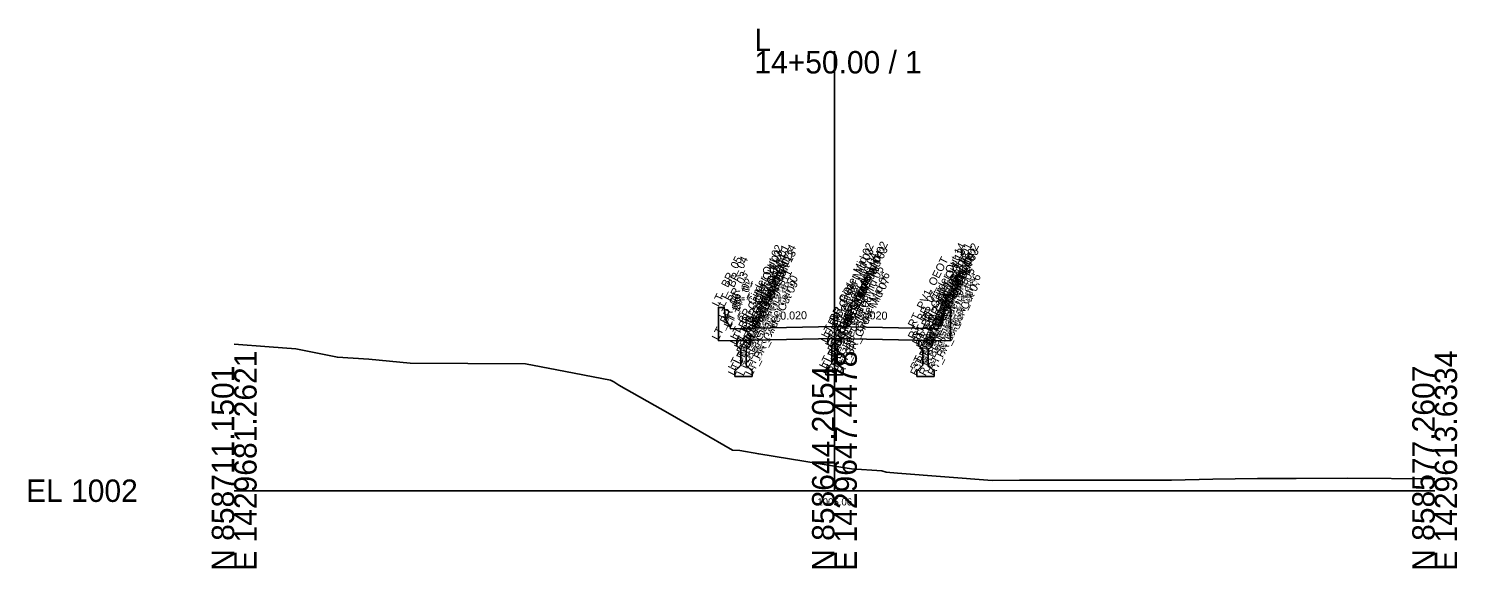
# Model space of a CAD drawing. Extents: x -26 to 153, y -10 to 13058.
# Drawn here: x -25.7 to 152.8, y 5990.3 to 6057.7 of the extents above; entities that cross this region are included whole.
import ezdxf

# ---------------------------------------------------------------- set-up
doc = ezdxf.new("R2010")
doc.units = 0
for name, color, linetype in [('Default', 7, 'Continuous'), ('Exist Cross Section Cell', 7, 'Continuous'), ('Exist XS Ground Line', 7, 'Continuous'), ('Prop CMT Concrete Structures', 7, 'Continuous'), ('Prop CMT Subgrade Daylight Point', 7, 'Continuous'), ('Prop XS Dump Level', 7, 'Continuous'), ('Prop XS SE Text', 7, 'Continuous')]:
    doc.layers.add(name, color=color, linetype=linetype)

msp = doc.modelspace()

# ---------------------------------------------------------------- linework, layer by layer
at = {"layer": 'Exist Cross Section Cell'}
for p, q in [((75, 6000), (75, 6054.87)), ((0, 6000), (75, 6000)), ((75, 6000), (150, 6000))]:
    msp.add_line(p, q, dxfattribs=at)
at = {"layer": 'Exist XS Ground Line'}
msp.add_lwpolyline([(0, 6018.29), (4.38, 6017.97), (7.68, 6017.7), (12.9, 6016.65), (16.81, 6016.43), (22, 6015.9), (36.38, 6015.84), (40.32, 6015.08), (47.01, 6013.78), (47.44, 6013.6), (48.07, 6013.16), (54.18, 6009.7), (62.26, 6005.07), (63.18, 6005), (65.54, 6004.59), (75, 6003.06), (77.15, 6002.71), (80.93, 6002.5), (81.45, 6002.31), (82.89, 6002.2), (94.71, 6001.27), (98.12, 6001.3), (104.03, 6001.31), (117.11, 6001.33), (122.27, 6001.45), (127.85, 6001.51), (132.7, 6001.52), (139.13, 6001.57), (150, 6001.48)], dxfattribs=at)
at = {"layer": 'Prop CMT Concrete Structures'}
for points in [[(75, 6020.48), (65, 6020.28), (62, 6020.22), (61.99, 6020.47), (61.41, 6021.3), (61.24, 6022.88), (60.5, 6022.88), (60.5, 6018.69)], [(75, 6020.48), (85, 6020.28), (88, 6020.22), (88.01, 6020.47), (88.59, 6021.3), (88.76, 6022.88), (89.5, 6022.88), (89.5, 6018.69)], [(75, 6018.98), (75, 6020.48)], [(75, 6018.98), (75, 6020.48)], [(60.5, 6018.69), (65, 6018.78), (75, 6018.98)], [(64.46, 6018.77), (63.62, 6018.75), (62.79, 6018.73)], [(62.79, 6018.73), (62.79, 6018.08)], [(64.46, 6018.08), (64.46, 6018.77)], [(75, 6018.98), (74.17, 6018.96)], [(74.17, 6018.96), (74.17, 6018.31)], [(75, 6014.48), (75, 6018.98)], [(75, 6018.98), (75.83, 6018.96)], [(75, 6014.48), (75, 6018.98)], [(89.5, 6018.69), (85, 6018.78), (75, 6018.98)], [(75.83, 6018.96), (75.83, 6018.31)], [(85.54, 6018.77), (86.38, 6018.75), (87.21, 6018.73)], [(85.54, 6018.08), (85.54, 6018.77)], [(87.21, 6018.73), (87.21, 6018.08)], [(62.79, 6018.08), (63.29, 6017.58)], [(63.29, 6017.58), (63.29, 6015.67)], [(63.96, 6017.58), (64.46, 6018.08)], [(63.96, 6015.67), (63.96, 6017.58)], [(74.17, 6018.31), (74.67, 6017.81)], [(74.67, 6017.81), (74.67, 6015.89)], [(75.83, 6018.31), (75.33, 6017.81)], [(75.33, 6017.81), (75.33, 6015.89)], [(86.04, 6017.58), (85.54, 6018.08)], [(86.04, 6015.67), (86.04, 6017.58)], [(87.21, 6018.08), (86.71, 6017.58)], [(86.71, 6017.58), (86.71, 6015.67)], [(63.29, 6015.67), (62.54, 6014.92)], [(62.54, 6014.92), (62.54, 6014.25)], [(64.71, 6014.92), (63.96, 6015.67)], [(64.71, 6014.25), (64.71, 6014.92)], [(74.67, 6015.89), (73.92, 6015.14)], [(73.92, 6015.14), (73.92, 6014.48)], [(75.33, 6015.89), (76.08, 6015.14)], [(76.08, 6015.14), (76.08, 6014.48)], [(85.29, 6014.92), (86.04, 6015.67)], [(85.29, 6014.25), (85.29, 6014.92)], [(86.71, 6015.67), (87.46, 6014.92)], [(87.46, 6014.92), (87.46, 6014.25)], [(62.54, 6014.25), (63.62, 6014.25), (64.71, 6014.25)], [(73.92, 6014.48), (75, 6014.48)], [(76.08, 6014.48), (75, 6014.48)], [(87.46, 6014.25), (86.38, 6014.25), (85.29, 6014.25)]]:
    msp.add_lwpolyline(points, dxfattribs=at)

# ---------------------------------------------------------------- texts
at = {"layer": 'Default'}
msp.add_text('-', height=0.0001, dxfattribs=at).set_placement((0, 6000))
at = {"layer": 'Exist Cross Section Cell'}
for s, p in [('L', (65, 6054.87)), ('14+50.00 / 1', (65, 6052.07)), ('EL 1002', (-26, 5998.6))]:
    msp.add_text(s, height=2.8, dxfattribs=at).set_placement(p)
for s, p in [('E 1429681.2621', (2.8, 5990)), ('E 1429647.4478', (77.8, 5990)), ('E 1429613.6334', (152.8, 5990)), ('N 858711.1501', (0, 5990)), ('N 858644.2054', (75, 5990)), ('N 858577.2607', (150, 5990))]:
    msp.add_text(s, height=2.8, rotation=90, dxfattribs=at).set_placement(p)
at = {"layer": 'Prop CMT Subgrade Daylight Point'}
msp.add_text('1005.06', height=0.9, dxfattribs=at).set_placement((72.86, 5998.16))
at = {"layer": 'Prop XS Dump Level'}
for s, p in [('LT_BR_Girder Mid 02', (74.17, 6018.96)), ('RT_BR_Girder Mid 02', (75.83, 6018.96)), ('RT_BR_Girder Out 14', (85.54, 6018.77)), ('RT_BR_Girder Out 02', (87.21, 6018.73)), ('LT_ BR_05', (60.5, 6022.88)), ('LT_ BR_04', (61.24, 6022.88)), ('LT_BR_Girder Out 02', (62.79, 6018.73)), ('LT_BR_Girder Out 03', (62.79, 6018.08)), ('LT_BR_Girder Out 04', (63.29, 6017.58)), ('LT_BR_Girder Out 01', (63.62, 6018.75)), ('LT_BR_Girder Out 12', (63.96, 6017.58)), ('LT_BR_Girder Out 14', (64.46, 6018.77)), ('LT_BR_Girder Out 13', (64.46, 6018.08)), ('LT_PV1_OEOT', (65, 6020.28)), ('LT_BR_Girder Mid 03', (74.17, 6018.31)), ('LT_BR_Girder Mid 04', (74.67, 6017.81)), ('RT_BR_Girder Mid 04', (75.33, 6017.81)), ('RT_BR_Girder Mid 03', (75.83, 6018.31)), ('RT_PV1_OEOT', (85, 6020.28)), ('RT_BR_Girder Out 13', (85.54, 6018.08)), ('RT_BR_Girder Out 12', (86.04, 6017.58)), ('RT_BR_Girder Out 01', (86.38, 6018.75)), ('RT_BR_Girder Out 04', (86.71, 6017.58)), ('RT_BR_Girder Out 03', (87.21, 6018.08)), ('RT_ BR_04', (88.76, 6022.88)), ('RT_ BR_05', (89.5, 6022.88)), ('LT_BR_03', (61.41, 6021.3)), ('LT_BR_Girder Out 05', (63.29, 6015.67)), ('LT_BR_Girder Out 11', (63.96, 6015.67)), ('LT_BR_Girder Mid 05', (74.67, 6015.89)), ('RT_BR_Girder Mid 05', (75.33, 6015.89)), ('RT_BR_Girder Mid 06', (76.08, 6015.14)), ('RT_BR_Girder Out 11', (86.04, 6015.67)), ('RT_BR_Girder Out 05', (86.71, 6015.67)), ('RT_BR_03', (88.59, 6021.3)), ('LT_BR_02', (61.99, 6020.47)), ('LT_BR_01', (62, 6020.22)), ('LT_BR_Girder Out 06', (62.54, 6014.92)), ('LT_BR_Girder Out 07', (62.54, 6014.25)), ('LT_BR_Girder Out 08', (63.62, 6014.25)), ('LT_BR_Girder Out 10', (64.71, 6014.92)), ('LT_BR_Girder Out 09', (64.71, 6014.25)), ('LT_BR_Girder Mid 06', (73.92, 6015.14)), ('LT_BR_Girder Mid 07', (73.92, 6014.48)), ('PV1_PGL', (75, 6020.48)), ('RT_BR_Girder Mid 07', (76.08, 6014.48)), ('RT_BR_Girder Out 10', (85.29, 6014.92)), ('RT_BR_Girder Out 09', (85.29, 6014.25)), ('RT_BR_Girder Out 08', (86.38, 6014.25)), ('RT_BR_Girder Out 06', (87.46, 6014.92)), ('RT_BR_Girder Out 07', (87.46, 6014.25)), ('RT_BR_01', (88, 6020.22)), ('RT_BR_02', (88.01, 6020.47)), ('LT_BR_06', (60.5, 6018.69)), ('LT_BR_07', (65, 6018.78)), ('BR_Girder Mid 08', (75, 6014.48)), ('BR_PGL', (75, 6018.98)), ('RT_BR_07', (85, 6018.78)), ('RT_BR_06', (89.5, 6018.69))]:
    msp.add_text(s, height=1, rotation=63.5833, dxfattribs=at).set_placement(p)
at = {"layer": 'Prop XS SE Text'}
for rotation, p in [(1.1458, (68.23, 6021.34)), (358.8542, (78.27, 6021.41))]:
    msp.add_text('0.020', height=1, rotation=rotation, dxfattribs=at).set_placement(p)

doc.saveas('drawing.dxf')
